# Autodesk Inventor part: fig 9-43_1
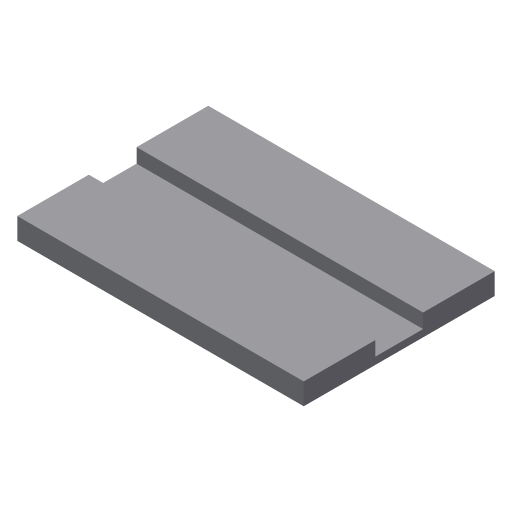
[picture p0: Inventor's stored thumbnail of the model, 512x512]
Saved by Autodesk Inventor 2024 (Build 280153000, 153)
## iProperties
Created: 2013-03
Part Number: fig 9-43_1
Material: Generic
Document SubType Name: Modeling
Designer: CADCIM
Density: 1 g/cm^3
Appearance: Default
Author: CADCIM
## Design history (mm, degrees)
sketch "Sketch1"
  geometry: L1 (-12.966, 10)-(17.034, 10); L2 (17.034, 10)-(17.034, -10); L3 (17.034, -10)-(-12.966, -10); L4 (-12.966, -10)-(-12.966, 10); 1 further point
  constraints: 8 end point, 2 parallel, 1 horizontal, 1 perpendicular
  dimensions: "d0" = 30 distance of L1.start L1.end; "d2" = 20 distance of L1.end L2.end
extrude "Extrusion1" new body sketch "Sketch1" distance "d3" = 2.25; taper "d4" = 0 deg
sketch "Sketch2"
  geometry: L1 (-12.966, 10)-(-12.966, -10) reference; L2 (-12.966, 2.498)-(87.034, 2.498); L3 (87.034, 2.498)-(87.034, -2.502); L4 (87.034, -2.502)-(-12.966, -2.502); L5 (-12.966, -2.502)-(-12.966, 2.498); 1 further point
  constraints: 8 end point, 2 parallel, 1 horizontal, 1 perpendicular, 1 point on line
  dimensions: "d5" = 5 distance of L2.end L3.end; "d7" = 100 distance of L2.start L2.end
extrude "Extrusion2" cut sketch "Sketch2" distance "d8" = 1.5; taper "d9" = 0 deg
body "Solid1"
